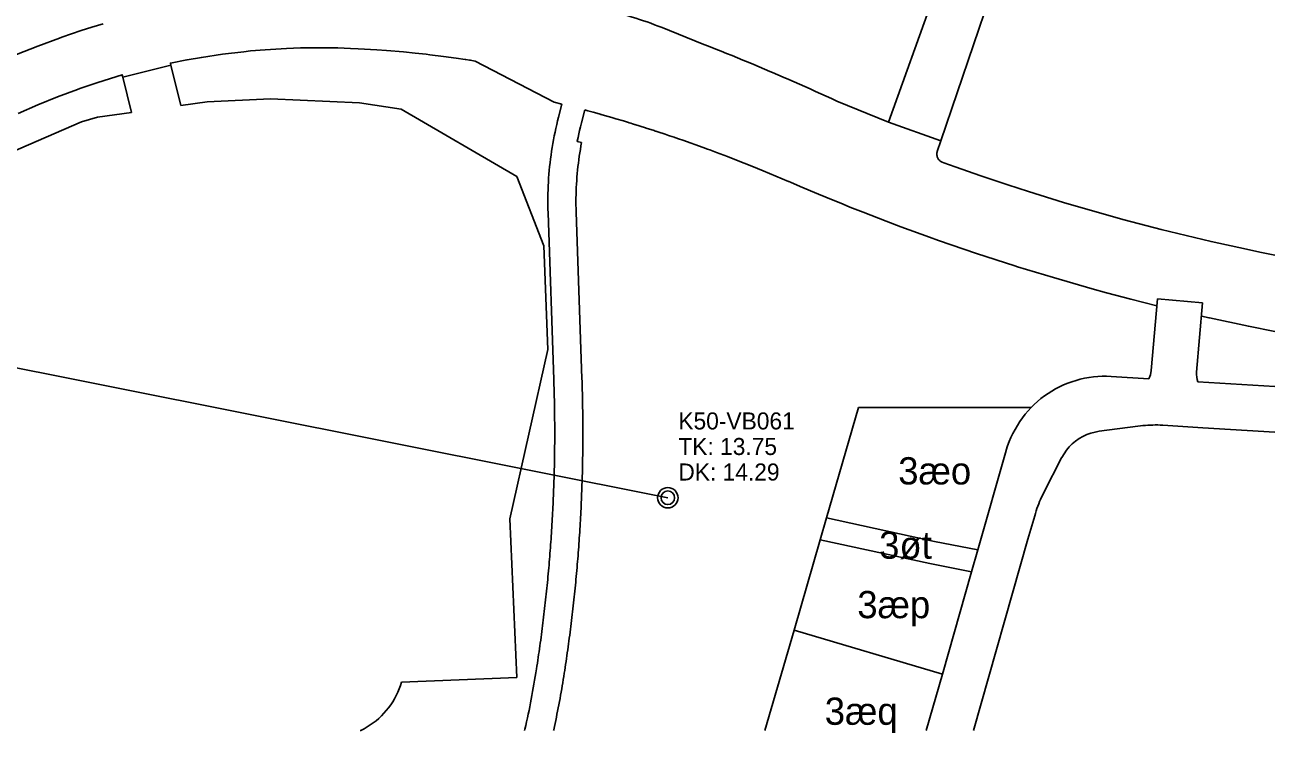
# Model space of a CAD drawing. Extents: x 702630 to 703245, y 6205279 to 6205714.
# Drawn here: x 702969.7 to 703245.1, y 6205391.5 to 6205547.5 of the extents above; entities that cross this region are included whole.
import ezdxf

# ---------------------------------------------------------------- set-up
doc = ezdxf.new("R2010")
doc.units = 0
for name, color, linetype in [('Brønd', 7, 'Continuous'), ('Brønd_Text', 7, 'Continuous'), ('Dæksel', 7, 'Continuous'), ('Matrikelnummer', 7, 'Continuous'), ('Matrikelnummer punkt', 7, 'Continuous'), ('Matrikelskel Almindeligt', 7, 'Continuous'), ('Matrikelskel Vej', 7, 'Continuous'), ('Optaget vej', 7, 'Continuous'), ('Trykledning', 7, 'Continuous')]:
    doc.layers.add(name, color=color, linetype=linetype)

msp = doc.modelspace()

# ---------------------------------------------------------------- linework, layer by layer
at = {"layer": 'Brønd'}
msp.add_line((703111.36, 6205443.32), (703111.36, 6205443.32), dxfattribs=at)
msp.add_circle((703111.36, 6205443.32), 2.25, dxfattribs=at)
at = {"layer": 'Dæksel'}
msp.add_line((703111.36, 6205443.32), (703111.36, 6205443.32), dxfattribs=at)
msp.add_circle((703111.36, 6205443.32), 1.5, dxfattribs=at)
at = {"layer": 'Matrikelnummer punkt'}
for p, q in [((703167.89, 6205449.25), (703167.89, 6205449.25)), ((703162.29, 6205432.88), (703162.29, 6205432.88)), ((703158.88, 6205419.78), (703158.88, 6205419.78)), ((703151.76, 6205396.29), (703151.76, 6205396.29))]:
    msp.add_line(p, q, dxfattribs=at)
at = {"layer": 'Matrikelskel Almindeligt'}
for p, q in [((703160.01, 6205526.05), (703171.89, 6205559.35)), ((703183.8, 6205558.17), (703171.51, 6205521.95)), ((703001.87, 6205538.64), (703004.06, 6205529.77)), ((702993.22, 6205528.24), (702991.3, 6205536.02)), ((703004.06, 6205529.77), (703009.88, 6205530.59)), ((703009.88, 6205530.59), (703023.83, 6205531.19)), ((703023.83, 6205531.19), (703043.41, 6205530.34)), ((703043.41, 6205530.34), (703052.58, 6205528.94)), ((702985.72, 6205527.19), (702993.22, 6205528.24)), ((703052.58, 6205528.94), (703078.08, 6205514.11)), ((702966.64, 6205519.43), (702982.18, 6205526.16)), ((702985.72, 6205527.19), (702982.18, 6205526.16)), ((703078.08, 6205514.11), (703084.01, 6205498.81)), ((703084.01, 6205498.81), (703084.93, 6205476.02)), ((703084.93, 6205476.02), (703076.54, 6205438.68)), ((703153.37, 6205463.17), (703146.34, 6205438.88)), ((703191.41, 6205463.2), (703153.37, 6205463.17)), ((703076.54, 6205438.68), (703078.08, 6205403.72)), ((703144.94, 6205434.06), (703139.17, 6205414.11)), ((703139.17, 6205414.11), (703132.77, 6205392)), ((703171.85, 6205404.44), (703139.17, 6205414.11)), ((703078.08, 6205403.72), (703052.68, 6205402.71))]:
    msp.add_line(p, q, dxfattribs=at)
msp.add_lwpolyline([(703043.59, 6205392), (703043.73, 6205392.06), (703044.44, 6205392.43), (703045.13, 6205392.82), (703045.8, 6205393.25), (703046.45, 6205393.71), (703047.08, 6205394.2), (703047.69, 6205394.71), (703048.27, 6205395.26), (703048.82, 6205395.83), (703049.34, 6205396.43), (703049.84, 6205397.05), (703050.31, 6205397.69), (703050.75, 6205398.36), (703051.16, 6205399.04), (703051.53, 6205399.74), (703051.87, 6205400.46), (703052.17, 6205401.2), (703052.45, 6205401.95), (703052.68, 6205402.71)], dxfattribs=at)
at = {"layer": 'Matrikelskel Vej'}
for p, q in [((702991.3, 6205536.02), (703001.87, 6205538.64)), ((703160.01, 6205526.05), (703171.51, 6205521.95)), ((703219.22, 6205487.13), (703217.85, 6205471.37)), ((703219.22, 6205487.13), (703229.18, 6205486.26)), ((703229.18, 6205486.26), (703227.86, 6205470.99)), ((703217.32, 6205469.52), (703209.01, 6205470.04)), ((703228.14, 6205468.85), (703245.13, 6205467.8)), ((703206.43, 6205457.96), (703214.92, 6205459.11)), ((703229.23, 6205458.76), (703220.41, 6205459.31)), ((703245.13, 6205457.77), (703229.23, 6205458.76)), ((703185.88, 6205453.71), (703179.65, 6205431.84)), ((703194.21, 6205444.46), (703198.12, 6205452.08)), ((703190.71, 6205434.17), (703192.19, 6205439.35)), ((703146.34, 6205438.88), (703144.94, 6205434.06)), ((703170.11, 6205433.71), (703146.34, 6205438.88)), ((703169.1, 6205428.81), (703144.94, 6205434.06)), ((703179.65, 6205431.84), (703170.11, 6205433.71)), ((703190.71, 6205434.17), (703178.7, 6205392)), ((703178.28, 6205427.01), (703179.65, 6205431.84)), ((703178.28, 6205427.01), (703169.1, 6205428.81)), ((703178.28, 6205427.01), (703171.85, 6205404.44)), ((703171.85, 6205404.44), (703168.3, 6205392))]:
    msp.add_line(p, q, dxfattribs=at)
for points in [[(703209.01, 6205470.04), (703208.04, 6205470.08), (703207.06, 6205470.08), (703206.09, 6205470.03), (703205.12, 6205469.95), (703204.16, 6205469.82), (703203.2, 6205469.65), (703202.24, 6205469.43), (703201.3, 6205469.18), (703200.38, 6205468.89), (703199.46, 6205468.55), (703198.56, 6205468.18), (703197.68, 6205467.77), (703196.81, 6205467.32), (703195.97, 6205466.83), (703195.15, 6205466.31), (703194.35, 6205465.75), (703193.57, 6205465.16), (703192.83, 6205464.54), (703192.1, 6205463.88), (703191.41, 6205463.2)], [(703217.32, 6205469.52), (703217.68, 6205470.42), (703217.85, 6205471.37)], [(703227.86, 6205470.99), (703227.84, 6205470.45), (703227.88, 6205469.91), (703227.98, 6205469.37), (703228.14, 6205468.85)], [(703191.41, 6205463.2), (703190.74, 6205462.46), (703190.1, 6205461.7), (703189.49, 6205460.91), (703188.91, 6205460.09), (703188.37, 6205459.25), (703187.87, 6205458.39), (703187.4, 6205457.51), (703186.97, 6205456.61), (703186.58, 6205455.69), (703186.23, 6205454.76), (703185.92, 6205453.81), (703185.88, 6205453.71)], [(703220.41, 6205459.31), (703219.86, 6205459.33), (703219.31, 6205459.35), (703218.76, 6205459.35), (703218.21, 6205459.34), (703217.66, 6205459.33), (703217.11, 6205459.3), (703216.57, 6205459.27), (703216.02, 6205459.23), (703215.47, 6205459.17), (703214.92, 6205459.11)], [(703206.43, 6205457.96), (703205.49, 6205457.8), (703204.58, 6205457.55), (703203.68, 6205457.22), (703202.82, 6205456.82), (703201.99, 6205456.34), (703201.21, 6205455.79), (703200.48, 6205455.18), (703199.81, 6205454.51), (703199.2, 6205453.78), (703198.65, 6205453), (703198.17, 6205452.18), (703198.12, 6205452.08)], [(703194.21, 6205444.46), (703193.96, 6205443.97), (703193.72, 6205443.47), (703193.5, 6205442.97), (703193.28, 6205442.47), (703193.07, 6205441.96), (703192.88, 6205441.44), (703192.69, 6205440.93), (703192.51, 6205440.41), (703192.35, 6205439.88), (703192.19, 6205439.35)]]:
    msp.add_lwpolyline(points, dxfattribs=at)
at = {"layer": 'Optaget vej'}
for p, q in [((703118.92, 6205543.37), (703110.08, 6205546.92)), ((703087.29, 6205527.2), (703088.04, 6205530.08)), ((703160.01, 6205526.05), (703148.58, 6205530.73)), ((703093.07, 6205528.79), (703092.32, 6205525.9)), ((703171.51, 6205521.95), (703170.74, 6205519.64)), ((703091.39, 6205521.79), (703092.38, 6205521.6)), ((703086.24, 6205469.4), (703084.97, 6205506.07)), ((703091.17, 6205506.28), (703092.44, 6205469.62))]:
    msp.add_line(p, q, dxfattribs=at)
for points in [[(703110.08, 6205546.92), (703109.27, 6205547.24), (703108.45, 6205547.55), (703107.63, 6205547.86), (703106.8, 6205548.15), (703105.97, 6205548.44), (703105.14, 6205548.72), (703104.31, 6205548.98), (703103.47, 6205549.24), (703102.63, 6205549.49), (703101.78, 6205549.73), (703100.94, 6205549.96), (703100.09, 6205550.18), (703099.88, 6205550.24), (703099.67, 6205550.29)], [(702986.93, 6205547.73), (702984.49, 6205547), (702982.09, 6205546.25), (702977.88, 6205544.83), (702977.3, 6205544.62), (702972.55, 6205542.86), (702967.86, 6205540.96)], [(703088.04, 6205530.08), (703086.32, 6205530.51), (703068.94, 6205539.52), (703068.19, 6205539.66), (703067.86, 6205539.72), (703067.65, 6205539.75), (703066.89, 6205539.87), (703066.68, 6205539.91), (703064.7, 6205540.19), (703061.95, 6205540.56), (703058.91, 6205540.93), (703058.09, 6205541.03), (703055.69, 6205541.29), (703053.1, 6205541.54), (703049.41, 6205541.85), (703047.28, 6205542), (703043.12, 6205542.25), (703041.44, 6205542.32), (703038.66, 6205542.42), (703036.78, 6205542.46), (703036.74, 6205542.46), (703032.03, 6205542.46), (703030.42, 6205542.42), (703027.33, 6205542.31), (703022.63, 6205542.03), (703019.41, 6205541.76), (703017.95, 6205541.61), (703013.27, 6205541.05), (703008.62, 6205540.35), (703005.47, 6205539.8), (703005.38, 6205539.78), (703001.76, 6205539.1), (703001.87, 6205538.64)], [(703148.58, 6205530.73), (703147.4, 6205531.27), (703146.23, 6205531.8), (703145.06, 6205532.34), (703143.88, 6205532.87), (703142.7, 6205533.4), (703141.53, 6205533.92), (703140.35, 6205534.45), (703139.17, 6205534.96), (703137.99, 6205535.48), (703136.8, 6205536), (703135.62, 6205536.51), (703134.43, 6205537.01), (703133.84, 6205537.27), (703132.65, 6205537.77), (703131.46, 6205538.27), (703130.28, 6205538.77), (703129.08, 6205539.27), (703127.89, 6205539.76), (703126.7, 6205540.25), (703125.51, 6205540.74), (703124.31, 6205541.22), (703123.11, 6205541.71), (703121.92, 6205542.18), (703120.72, 6205542.66), (703119.52, 6205543.13), (703118.92, 6205543.37)], [(702991.3, 6205536.02), (702991.17, 6205536.52), (702985.77, 6205534.82), (702981.85, 6205533.5), (702981.31, 6205533.31), (702976.9, 6205531.67), (702972.54, 6205529.9), (702968.23, 6205528.01)], [(703093.07, 6205528.79), (703093.72, 6205528.61), (703094.9, 6205528.28), (703096.27, 6205527.9), (703096.47, 6205527.84), (703096.62, 6205527.8), (703096.68, 6205527.78), (703097.41, 6205527.57), (703099.02, 6205527.1), (703099.9, 6205526.84), (703101.56, 6205526.34), (703102.71, 6205525.99), (703102.88, 6205525.94), (703103.17, 6205525.85), (703103.18, 6205525.84), (703103.61, 6205525.71), (703104.05, 6205525.57), (703104.1, 6205525.56), (703106.41, 6205524.83), (703106.62, 6205524.76), (703108.33, 6205524.21), (703108.58, 6205524.13), (703108.7, 6205524.09), (703109.17, 6205523.94), (703110.76, 6205523.41), (703111.52, 6205523.15), (703111.71, 6205523.09), (703112.73, 6205522.74), (703112.93, 6205522.67), (703113.12, 6205522.61), (703113.74, 6205522.39), (703114.66, 6205522.08), (703119.14, 6205520.49), (703120.1, 6205520.14), (703120.59, 6205519.96), (703122.12, 6205519.39), (703124.5, 6205518.49), (703126.47, 6205517.73), (703129.84, 6205516.4), (703131.12, 6205515.88), (703132.39, 6205515.36), (703137.97, 6205513.01), (703138.02, 6205512.99), (703138.39, 6205512.83), (703140.53, 6205511.91), (703144.53, 6205510.22), (703146.18, 6205509.53), (703149.96, 6205507.99), (703151.49, 6205507.37), (703154.4, 6205506.22), (703159.47, 6205504.26), (703162.68, 6205503.05), (703168.99, 6205500.74), (703169.05, 6205500.72), (703171.01, 6205500.02), (703179.39, 6205497.14), (703187.82, 6205494.41), (703188.4, 6205494.22), (703196.3, 6205491.82), (703204.82, 6205489.38), (703208.01, 6205488.5), (703213.38, 6205487.08), (703219.09, 6205485.64)], [(703084.97, 6205506.07), (703084.95, 6205506.92), (703084.93, 6205507.78), (703084.93, 6205508.63), (703084.93, 6205509.48), (703084.95, 6205510.33), (703084.97, 6205511.19), (703085, 6205512.04), (703085.05, 6205512.89), (703085.1, 6205513.74), (703085.17, 6205514.59), (703085.24, 6205515.44), (703085.32, 6205516.29), (703085.42, 6205517.14), (703085.52, 6205517.99), (703085.63, 6205518.83), (703085.75, 6205519.68), (703085.89, 6205520.52), (703086.03, 6205521.36), (703086.18, 6205522.2), (703086.34, 6205523.04), (703086.51, 6205523.88), (703086.69, 6205524.71), (703086.88, 6205525.54), (703087.08, 6205526.37), (703087.29, 6205527.2)], [(703092.32, 6205525.9), (703092.12, 6205525.08), (703091.92, 6205524.26), (703091.75, 6205523.52), (703091.58, 6205522.7), (703091.41, 6205521.87), (703091.39, 6205521.79)], [(703092.38, 6205521.6), (703092.23, 6205520.85), (703092.1, 6205520.09), (703091.97, 6205519.33), (703091.86, 6205518.57), (703091.75, 6205517.8), (703091.65, 6205517.04), (703091.56, 6205516.28), (703091.47, 6205515.51), (703091.4, 6205514.75), (703091.34, 6205513.98), (703091.28, 6205513.21), (703091.23, 6205512.44), (703091.19, 6205511.67), (703091.16, 6205510.9), (703091.14, 6205510.13), (703091.13, 6205509.36), (703091.13, 6205508.59), (703091.13, 6205507.82), (703091.15, 6205507.05), (703091.17, 6205506.28)], [(703170.74, 6205519.64), (703170.69, 6205519.48), (703170.66, 6205519.31), (703170.64, 6205519.14), (703170.64, 6205518.97), (703170.65, 6205518.8), (703170.68, 6205518.64), (703170.72, 6205518.47), (703170.78, 6205518.31), (703170.85, 6205518.16), (703170.93, 6205518.01), (703171.03, 6205517.87), (703171.14, 6205517.74), (703171.26, 6205517.62), (703171.39, 6205517.51), (703171.53, 6205517.41), (703171.68, 6205517.33), (703171.83, 6205517.26)], [(703171.83, 6205517.26), (703172.2, 6205517.11), (703174.66, 6205516.24), (703180.31, 6205514.27), (703186.24, 6205512.27), (703190.85, 6205510.77), (703198.51, 6205508.39), (703204.92, 6205506.51), (703211.88, 6205504.55), (703220.08, 6205502.41), (703231.05, 6205499.76), (703238.86, 6205498.06), (703241.79, 6205497.44), (703245.13, 6205496.8)], [(703228.92, 6205483.32), (703230.61, 6205482.94), (703230.68, 6205482.93), (703239.28, 6205481.1), (703245.13, 6205479.96)], [(703092.44, 6205469.62), (703092.46, 6205468.97), (703092.48, 6205468.32), (703092.5, 6205467.66), (703092.52, 6205467.01), (703092.54, 6205466.36), (703092.55, 6205465.71), (703092.57, 6205465.06), (703092.58, 6205464.41), (703092.59, 6205463.75), (703092.6, 6205463.1), (703092.61, 6205462.45), (703092.62, 6205461.8), (703092.63, 6205461.15), (703092.63, 6205460.5), (703092.64, 6205459.84), (703092.64, 6205459.19), (703092.64, 6205458.54), (703092.64, 6205457.89), (703092.64, 6205457.24), (703092.64, 6205456.58), (703092.64, 6205455.93), (703092.64, 6205455.28), (703092.63, 6205454.63), (703092.62, 6205453.98), (703092.62, 6205453.33), (703092.61, 6205452.67), (703092.6, 6205452.02), (703092.59, 6205451.37), (703092.58, 6205450.72), (703092.56, 6205450.07), (703092.55, 6205449.42), (703092.53, 6205448.76), (703092.51, 6205448.11), (703092.49, 6205447.46), (703092.47, 6205446.81), (703092.45, 6205446.16), (703092.43, 6205445.51), (703092.41, 6205444.86), (703092.38, 6205444.2), (703092.36, 6205443.55), (703092.33, 6205442.9), (703092.3, 6205442.25), (703092.27, 6205441.6), (703092.24, 6205440.95), (703092.21, 6205440.3), (703092.17, 6205439.65), (703092.14, 6205439), (703092.1, 6205438.34), (703092.07, 6205437.69), (703092.03, 6205437.04), (703091.99, 6205436.39), (703091.95, 6205435.74), (703091.91, 6205435.09), (703091.86, 6205434.44), (703091.82, 6205433.79), (703091.77, 6205433.14), (703091.72, 6205432.49), (703091.68, 6205431.84), (703091.63, 6205431.19), (703091.58, 6205430.54), (703091.53, 6205429.89), (703091.47, 6205429.24), (703091.42, 6205428.59), (703091.36, 6205427.94), (703091.31, 6205427.29), (703091.25, 6205426.64), (703091.19, 6205425.99), (703091.13, 6205425.34), (703091.07, 6205424.7), (703091, 6205424.05), (703090.94, 6205423.4), (703090.87, 6205422.75), (703090.81, 6205422.1), (703090.74, 6205421.45), (703090.67, 6205420.81), (703090.6, 6205420.16), (703090.53, 6205419.51), (703090.46, 6205418.86), (703090.38, 6205418.21), (703090.31, 6205417.57), (703090.23, 6205416.92), (703090.15, 6205416.27), (703090.07, 6205415.63), (703089.99, 6205414.98), (703089.91, 6205414.33), (703089.83, 6205413.69), (703089.75, 6205413.04), (703089.66, 6205412.39), (703089.58, 6205411.75), (703089.49, 6205411.1), (703089.4, 6205410.46), (703089.31, 6205409.81), (703089.22, 6205409.16), (703089.13, 6205408.52), (703089.03, 6205407.87), (703088.94, 6205407.23), (703088.84, 6205406.58), (703088.75, 6205405.94), (703088.65, 6205405.29), (703088.55, 6205404.65)], [(703082.42, 6205405.6), (703082.52, 6205406.24), (703082.62, 6205406.87), (703082.71, 6205407.5), (703082.81, 6205408.13), (703082.9, 6205408.77), (703082.99, 6205409.4), (703083.08, 6205410.04), (703083.17, 6205410.67), (703083.26, 6205411.3), (703083.35, 6205411.94), (703083.43, 6205412.57), (703083.52, 6205413.21), (703083.6, 6205413.84), (703083.68, 6205414.48), (703083.76, 6205415.11), (703083.84, 6205415.75), (703083.92, 6205416.38), (703084, 6205417.02), (703084.07, 6205417.65), (703084.15, 6205418.29), (703084.22, 6205418.92), (703084.3, 6205419.56), (703084.37, 6205420.2), (703084.44, 6205420.83), (703084.51, 6205421.47), (703084.57, 6205422.1), (703084.64, 6205422.74), (703084.71, 6205423.38), (703084.77, 6205424.01), (703084.83, 6205424.65), (703084.9, 6205425.29), (703084.95, 6205425.93), (703085.02, 6205426.56), (703085.07, 6205427.2), (703085.13, 6205427.84), (703085.19, 6205428.48), (703085.24, 6205429.11), (703085.29, 6205429.75), (703085.34, 6205430.39), (703085.4, 6205431.03), (703085.45, 6205431.67), (703085.49, 6205432.3), (703085.54, 6205432.94), (703085.59, 6205433.58), (703085.63, 6205434.22), (703085.68, 6205434.86), (703085.72, 6205435.5), (703085.76, 6205436.13), (703085.8, 6205436.77), (703085.84, 6205437.41), (703085.88, 6205438.05), (703085.91, 6205438.69), (703085.95, 6205439.33), (703085.98, 6205439.97), (703086.02, 6205440.61), (703086.05, 6205441.25), (703086.08, 6205441.89), (703086.11, 6205442.53), (703086.13, 6205443.17), (703086.16, 6205443.8), (703086.19, 6205444.45), (703086.21, 6205445.08), (703086.23, 6205445.72), (703086.26, 6205446.36), (703086.28, 6205447), (703086.3, 6205447.64), (703086.32, 6205448.28), (703086.33, 6205448.92), (703086.35, 6205449.56), (703086.36, 6205450.2), (703086.38, 6205450.84), (703086.39, 6205451.48), (703086.4, 6205452.12), (703086.41, 6205452.76), (703086.42, 6205453.4), (703086.43, 6205454.04), (703086.43, 6205454.68), (703086.44, 6205455.32), (703086.44, 6205455.96), (703086.44, 6205456.6), (703086.44, 6205457.24), (703086.44, 6205457.88), (703086.44, 6205458.52), (703086.44, 6205459.16), (703086.44, 6205459.8), (703086.43, 6205460.44), (703086.43, 6205461.08), (703086.42, 6205461.72), (703086.41, 6205462.36), (703086.4, 6205463), (703086.39, 6205463.64), (703086.38, 6205464.28), (703086.37, 6205464.92), (703086.35, 6205465.56), (703086.34, 6205466.2), (703086.32, 6205466.84), (703086.3, 6205467.48), (703086.28, 6205468.12), (703086.26, 6205468.76), (703086.24, 6205469.4)], [(703079.82, 6205392), (703079.89, 6205392.31), (703080.07, 6205393.13), (703080.26, 6205393.96), (703080.43, 6205394.79), (703080.61, 6205395.61), (703080.78, 6205396.44), (703080.95, 6205397.27), (703081.11, 6205398.1), (703081.27, 6205398.93), (703081.43, 6205399.76), (703081.58, 6205400.6), (703081.73, 6205401.43), (703081.87, 6205402.26), (703082.02, 6205403.1), (703082.16, 6205403.93), (703082.29, 6205404.77), (703082.42, 6205405.6)], [(703088.55, 6205404.65), (703088.44, 6205403.95), (703088.33, 6205403.26), (703088.21, 6205402.57), (703088.1, 6205401.87), (703087.98, 6205401.18), (703087.86, 6205400.48), (703087.73, 6205399.79), (703087.61, 6205399.1), (703087.48, 6205398.41), (703087.35, 6205397.71), (703087.21, 6205397.02), (703087.08, 6205396.33), (703086.94, 6205395.64), (703086.8, 6205394.95), (703086.66, 6205394.26), (703086.51, 6205393.57), (703086.36, 6205392.88), (703086.22, 6205392.2), (703086.17, 6205392)]]:
    msp.add_lwpolyline(points, dxfattribs=at)
at = {"layer": 'Trykledning'}
msp.add_lwpolyline([(702957.06, 6205474.08), (703111.36, 6205443.32)], dxfattribs=at)

# ---------------------------------------------------------------- texts
at = {"layer": 'Brønd_Text'}
for s, p in [('K50-VB061', (703113.68, 6205458.37)), ('TK: 13.75', (703113.68, 6205452.74)), ('DK: 14.29', (703113.68, 6205447.12))]:
    msp.add_text(s, height=3.75, dxfattribs=at).set_placement(p)
at = {"layer": 'Matrikelnummer'}
for s, p in [('3æo', (703162.13, 6205446.25)), ('3øt', (703157.93, 6205429.88)), ('3æp', (703153.11, 6205416.78)), ('3æq', (703145.94, 6205393.29))]:
    msp.add_text(s, height=6, dxfattribs=at).set_placement(p)

doc.saveas('drawing.dxf')
